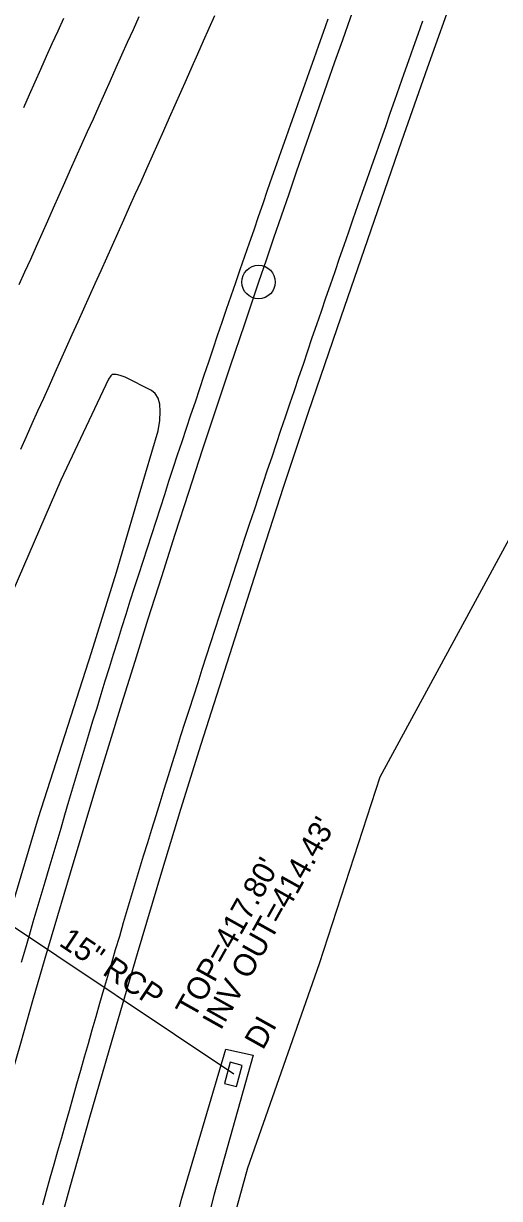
# Model space of a CAD drawing. Extents: x 2074109 to 2077820, y 741079 to 746031.
# Drawn here: x 2076090.1 to 2076175.2, y 744152.4 to 744362.7 of the extents above; entities that cross this region are included whole.
import ezdxf

# ---------------------------------------------------------------- set-up
doc = ezdxf.new("R2010")
doc.units = 0
for name, color, linetype in [('Exist Horizontal Alignment', 7, 'Continuous'), ('Exist Horizontal Alignment Point', 7, 'Continuous'), ('Exist Roads EOP', 7, 'Continuous'), ('Exist Roads EOT', 7, 'Continuous'), ('Exist Structure Minor Drop Inlet', 7, 'Continuous'), ('Exist Structure Minor Drop Inlet Text', 7, 'Continuous'), ('Exist Structure Minor Drop Inlet Top Elevation', 7, 'Continuous'), ('Exist Structure Minor Paved Ditch or Gutter', 7, 'Continuous'), ('Exist Structure Minor Pipes RCP 15 Inch', 7, 'Continuous'), ('Exist Structure Minor Pipes RCP 15 Inch Invert', 7, 'Continuous'), ('Exist Structure Minor Pipes RCP 15 Inch Text', 7, 'Continuous'), ('Exist Vegetation Woods Line', 7, 'Continuous')]:
    doc.layers.add(name, color=color, linetype=linetype)

msp = doc.modelspace()

# ---------------------------------------------------------------- linework, layer by layer
at = {"layer": 'Exist Horizontal Alignment'}
for centre, radius, start, end in [((2065746.77, 748969.72), 11283.45, 330.581241, 339.398504), ((2074798.58, 745361.18), 1469.76, 306.18995, 339.08912), ((2080198.26, 742932.72), 4295.13, 157.65302, 161.20687), ((2078824.82, 743400.1), 2844.34, 161.20687, 171.42865)]:
    msp.add_arc(centre, radius, start, end, dxfattribs=at)
at = {"layer": 'Exist Horizontal Alignment Point'}
msp.add_circle((2076132.11, 744316.41), 3, dxfattribs=at)
at = {"layer": 'Exist Roads EOP'}
for points in [[(2076167.22, 744368.58), (2076162.26, 744354.66), (2076157.69, 744341.6), (2076152.79, 744327.41), (2076146.82, 744310.11), (2076140.99, 744293.06), (2076136.52, 744279.63), (2076132.23, 744266.35), (2076126.92, 744249.74), (2076121.82, 744233.67), (2076118.17, 744222.02), (2076114.77, 744210.84), (2076110.43, 744196.2), (2076105.89, 744180.69), (2076101.92, 744166.94), (2076098.37, 744154.47), (2076095.13, 744142.81)], [(2076085.93, 744197.51), (2076092.78, 744220.6), (2076102.28, 744250.14), (2076106.7, 744264.53), (2076110.75, 744278.33), (2076114.15, 744289.79), (2076114.45, 744291.64), (2076114.55, 744293.24), (2076114.46, 744294.57), (2076114.16, 744295.65), (2076113.66, 744296.47), (2076112.97, 744297.02), (2076108.27, 744299.37), (2076107.56, 744299.64), (2076106.93, 744299.81), (2076106.65, 744299.86), (2076106.4, 744299.89), (2076106.16, 744299.88), (2076105.95, 744299.86), (2076105.68, 744299.63), (2076105.26, 744299.03), (2076096.79, 744280.96), (2076082.4, 744247.87)]]:
    msp.add_lwpolyline(points, dxfattribs=at)
at = {"layer": 'Exist Roads EOT'}
for points in [[(2076110.7, 744363.84), (2076109.68, 744361.55), (2076108.65, 744359.27), (2076107.63, 744356.99), (2076106.61, 744354.71), (2076105.59, 744352.43), (2076104.57, 744350.15), (2076103.55, 744347.87), (2076102.53, 744345.58), (2076101.5, 744343.3), (2076100.48, 744341.02), (2076099.46, 744338.74), (2076098.44, 744336.46), (2076097.42, 744334.17), (2076096.42, 744331.88), (2076095.41, 744329.6), (2076094.41, 744327.31), (2076093.38, 744325.03), (2076092.35, 744322.75), (2076091.32, 744320.47), (2076090.3, 744318.19), (2076089.27, 744315.91)], [(2076124.21, 744364.06), (2076123.21, 744361.77), (2076122.21, 744359.49), (2076121.2, 744357.2), (2076120.2, 744354.91), (2076119.19, 744352.62), (2076118.18, 744350.33), (2076117.16, 744348.05), (2076116.14, 744345.77), (2076115.12, 744343.48), (2076114.1, 744341.2), (2076113.08, 744338.92), (2076112.06, 744336.64), (2076111.04, 744334.35), (2076110.02, 744332.07), (2076109.01, 744329.79), (2076107.99, 744327.51), (2076106.97, 744325.22), (2076105.94, 744322.94), (2076104.91, 744320.67), (2076103.89, 744318.39), (2076102.86, 744316.11), (2076101.84, 744313.83), (2076100.81, 744311.55), (2076099.79, 744309.27), (2076098.76, 744306.99), (2076097.73, 744304.71), (2076096.71, 744302.43), (2076095.69, 744300.15), (2076094.66, 744297.86), (2076093.64, 744295.58), (2076092.62, 744293.3), (2076091.6, 744291.02), (2076090.58, 744288.74), (2076089.56, 744286.46)], [(2076089.73, 744194.73), (2076090.43, 744197.13), (2076091.14, 744199.53), (2076091.85, 744201.93), (2076092.56, 744204.32), (2076093.26, 744206.72), (2076093.97, 744209.12), (2076094.68, 744211.52), (2076095.38, 744213.91), (2076096.09, 744216.31), (2076096.8, 744218.71), (2076097.5, 744221.11), (2076098.21, 744223.51), (2076098.92, 744225.9), (2076099.62, 744228.3), (2076100.33, 744230.7), (2076101.04, 744233.1), (2076101.77, 744235.49), (2076102.5, 744237.88), (2076103.24, 744240.26), (2076103.98, 744242.65), (2076104.72, 744245.04), (2076105.45, 744247.43), (2076106.19, 744249.82), (2076106.93, 744252.21), (2076107.67, 744254.59), (2076108.42, 744256.98), (2076109.18, 744259.36), (2076109.95, 744261.74), (2076110.72, 744264.11), (2076111.49, 744266.49), (2076112.26, 744268.87), (2076113.02, 744271.25), (2076113.79, 744273.63), (2076114.56, 744276.01), (2076115.33, 744278.39), (2076116.1, 744280.77), (2076116.87, 744283.14), (2076117.64, 744285.52), (2076118.44, 744287.89), (2076119.23, 744290.26), (2076120.03, 744292.63), (2076120.82, 744295), (2076121.62, 744297.37), (2076122.42, 744299.74), (2076123.21, 744302.11), (2076124.01, 744304.48), (2076124.8, 744306.85), (2076125.6, 744309.22), (2076126.41, 744311.58), (2076127.23, 744313.94), (2076128.04, 744316.31), (2076128.85, 744318.67), (2076129.67, 744321.04), (2076130.48, 744323.4), (2076131.3, 744325.76), (2076132.11, 744328.13), (2076132.92, 744330.49), (2076133.74, 744332.85), (2076134.56, 744335.22), (2076135.39, 744337.57), (2076136.23, 744339.93), (2076137.06, 744342.29), (2076137.89, 744344.64), (2076138.73, 744347), (2076139.56, 744349.36), (2076140.39, 744351.71), (2076141.23, 744354.07), (2076142.06, 744356.43), (2076142.9, 744358.78), (2076143.73, 744361.14), (2076144.56, 744363.5)], [(2076097.23, 744363.58), (2076096.21, 744361.3), (2076095.18, 744359.02), (2076094.16, 744356.74), (2076093.14, 744354.46), (2076092.11, 744352.18), (2076091.09, 744349.9), (2076090.07, 744347.61)], [(2076161.41, 744363.07), (2076160.58, 744360.71), (2076159.75, 744358.35), (2076158.92, 744355.99), (2076158.09, 744353.64), (2076157.26, 744351.28), (2076156.43, 744348.92), (2076155.6, 744346.56), (2076154.78, 744344.2), (2076153.95, 744341.84), (2076153.12, 744339.48), (2076152.29, 744337.13), (2076151.46, 744334.77), (2076150.63, 744332.41), (2076149.8, 744330.05), (2076148.98, 744327.69), (2076148.17, 744325.33), (2076147.36, 744322.96), (2076146.54, 744320.6), (2076145.73, 744318.23), (2076144.91, 744315.87), (2076144.1, 744313.51), (2076143.29, 744311.14), (2076142.47, 744308.78), (2076141.66, 744306.42), (2076140.86, 744304.05), (2076140.06, 744301.68), (2076139.26, 744299.31), (2076138.46, 744296.94), (2076137.66, 744294.58), (2076136.86, 744292.21), (2076136.06, 744289.84), (2076135.26, 744287.47), (2076134.46, 744285.1), (2076133.67, 744282.73), (2076132.88, 744280.36), (2076132.09, 744277.99), (2076131.3, 744275.62), (2076130.51, 744273.24), (2076129.72, 744270.87), (2076128.93, 744268.5), (2076128.15, 744266.13), (2076127.38, 744263.75), (2076126.61, 744261.37), (2076125.84, 744258.99), (2076125.07, 744256.61), (2076124.3, 744254.24), (2076123.54, 744251.86), (2076122.77, 744249.48), (2076122, 744247.1), (2076121.23, 744244.72), (2076120.46, 744242.34), (2076119.69, 744239.96), (2076118.93, 744237.58), (2076118.18, 744235.2), (2076117.44, 744232.81), (2076116.7, 744230.42), (2076115.96, 744228.04), (2076115.21, 744225.65), (2076114.47, 744223.26), (2076113.73, 744220.88), (2076112.99, 744218.49), (2076112.24, 744216.1), (2076111.51, 744213.71), (2076110.8, 744211.32), (2076110.08, 744208.92), (2076109.37, 744206.53), (2076108.65, 744204.13), (2076107.94, 744201.74), (2076107.23, 744199.34), (2076106.51, 744196.94), (2076105.8, 744194.55), (2076105.09, 744192.15), (2076104.37, 744189.76), (2076103.69, 744187.35), (2076103.01, 744184.95), (2076102.32, 744182.54), (2076101.64, 744180.14), (2076100.96, 744177.74), (2076100.27, 744175.33), (2076099.59, 744172.93), (2076098.91, 744170.52), (2076098.23, 744168.12), (2076097.54, 744165.71), (2076096.86, 744163.31), (2076096.18, 744160.9), (2076095.49, 744158.5), (2076094.82, 744156.09), (2076094.16, 744153.68), (2076093.5, 744151.27)]]:
    msp.add_lwpolyline(points, dxfattribs=at)
at = {"layer": 'Exist Structure Minor Drop Inlet'}
msp.add_lwpolyline([(2076127.06, 744176.81), (2076126.05, 744173.04), (2076128.15, 744172.47), (2076129.16, 744176.25)], close=True, dxfattribs=at)
at = {"layer": 'Exist Structure Minor Paved Ditch or Gutter'}
msp.add_lwpolyline([(2076099.59, 744080.79), (2076109.53, 744117.53), (2076118.4, 744152.48), (2076126.24, 744179.16), (2076131.13, 744178.08), (2076124.16, 744153.21), (2076112.43, 744107.35), (2076105.12, 744079.29)], dxfattribs=at)
at = {"layer": 'Exist Structure Minor Pipes RCP 15 Inch'}
msp.add_line((2076077.02, 744208.59), (2076127.72, 744174.77), dxfattribs=at)
at = {"layer": 'Exist Vegetation Woods Line'}
msp.add_lwpolyline([(2076107.28, 744074.73), (2076130.2, 744157.92), (2076143.01, 744194.51), (2076153.86, 744227.89), (2076188.27, 744291.43), (2076195.28, 744310.48), (2076193.39, 744322.38), (2076193.24, 744336.15), (2076200.38, 744354.66), (2076208.43, 744372.83), (2076216.01, 744398.24), (2076232.65, 744436.02), (2076241.14, 744455.42), (2076252.42, 744480.93), (2076260.13, 744507.93), (2076277.39, 744547.61)], dxfattribs=at)

# ---------------------------------------------------------------- texts
at = {"layer": 'Exist Structure Minor Drop Inlet Text'}
msp.add_text('DI', height=4, rotation=60.7411, dxfattribs=at).set_placement((2076132.89, 744178.86))
at = {"layer": 'Exist Structure Minor Drop Inlet Top Elevation'}
msp.add_text("TOP=417.80'", height=4, rotation=60.7411, dxfattribs=at).set_placement((2076120.57, 744184.46))
at = {"layer": 'Exist Structure Minor Pipes RCP 15 Inch Invert'}
msp.add_text("INV OUT=414.43'", height=4, rotation=60.7411, dxfattribs=at).set_placement((2076125.35, 744182.39))
at = {"layer": 'Exist Structure Minor Pipes RCP 15 Inch Text'}
msp.add_text('15" RCP', height=4, rotation=326.2969, dxfattribs=at).set_placement((2076096.25, 744197.83))

doc.saveas('drawing.dxf')
